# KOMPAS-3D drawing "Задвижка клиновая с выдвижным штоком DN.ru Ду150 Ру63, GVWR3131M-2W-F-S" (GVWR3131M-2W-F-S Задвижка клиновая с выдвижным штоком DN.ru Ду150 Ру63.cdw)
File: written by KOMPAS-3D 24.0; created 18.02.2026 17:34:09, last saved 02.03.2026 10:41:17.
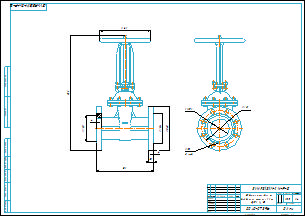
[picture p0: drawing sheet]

Document properties: art: D040-07396; Автор: R2D2; Форматы листов документа: A2; Полное имя файла: GVWR3131M-2W-F-S Задвижка клиновая с выдвижным штоком DN.ru Ду150 Ру63.m3d; Масса: 139; Наименование: Задвижка клиновая с выдвижным штоком DN.ru Ду150 Ру63; Количество листов документа: 1; Примечание: D040-07396

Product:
- Part/product: Задвижка клиновая с выдвижным штоком DN.ru Ду150 Ру63  | designation GVWR3131M-2W-F-S
    Масса: 139
    Раздел спецификации: Прочие изделия
    Форматы листов документа: A2
    Примечание: D040-07396
    additional columns: D040-07396

Referenced files in E:\Работа\Зайцев\Для компаса\: чертеж DN.ru А3.cdt
Referenced files in E:\Работа\Зайцев\GVWR3131M-2W-F-S Задвижка клиновая с выдвижным штоком DN.ru Ду50-200 Ру63\DN150\: GVWR3131M-2W-F-S Задвижка клиновая с выдвижным штоком DN.ru Ду150 Ру63.m3d
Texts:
  чертеж DN.ru А3.cdt
  Задвижка клиновая с
  выдвижным штоком DN.ru
  Ду150 Ру63
  GVWR3131M-2W-F-S
  Задвижка клиновая с выдвижным штоком DN.ru Ду150 Ру63
  GVWR3131M-2W-F-S Задвижка клиновая с выдвижным штоком DN.ru Ду150 Ру63
Dimensions and other numbers on the sheet: 1:4; 0; 1; 2; 139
